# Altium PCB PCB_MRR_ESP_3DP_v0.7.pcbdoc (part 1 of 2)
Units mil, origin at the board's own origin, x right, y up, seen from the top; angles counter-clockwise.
Board outline 5220 x 5030 mil, 2 copper layers (Top Layer, Bottom Layer); 131 components, 154 nets, 480 pads, 88 vias.
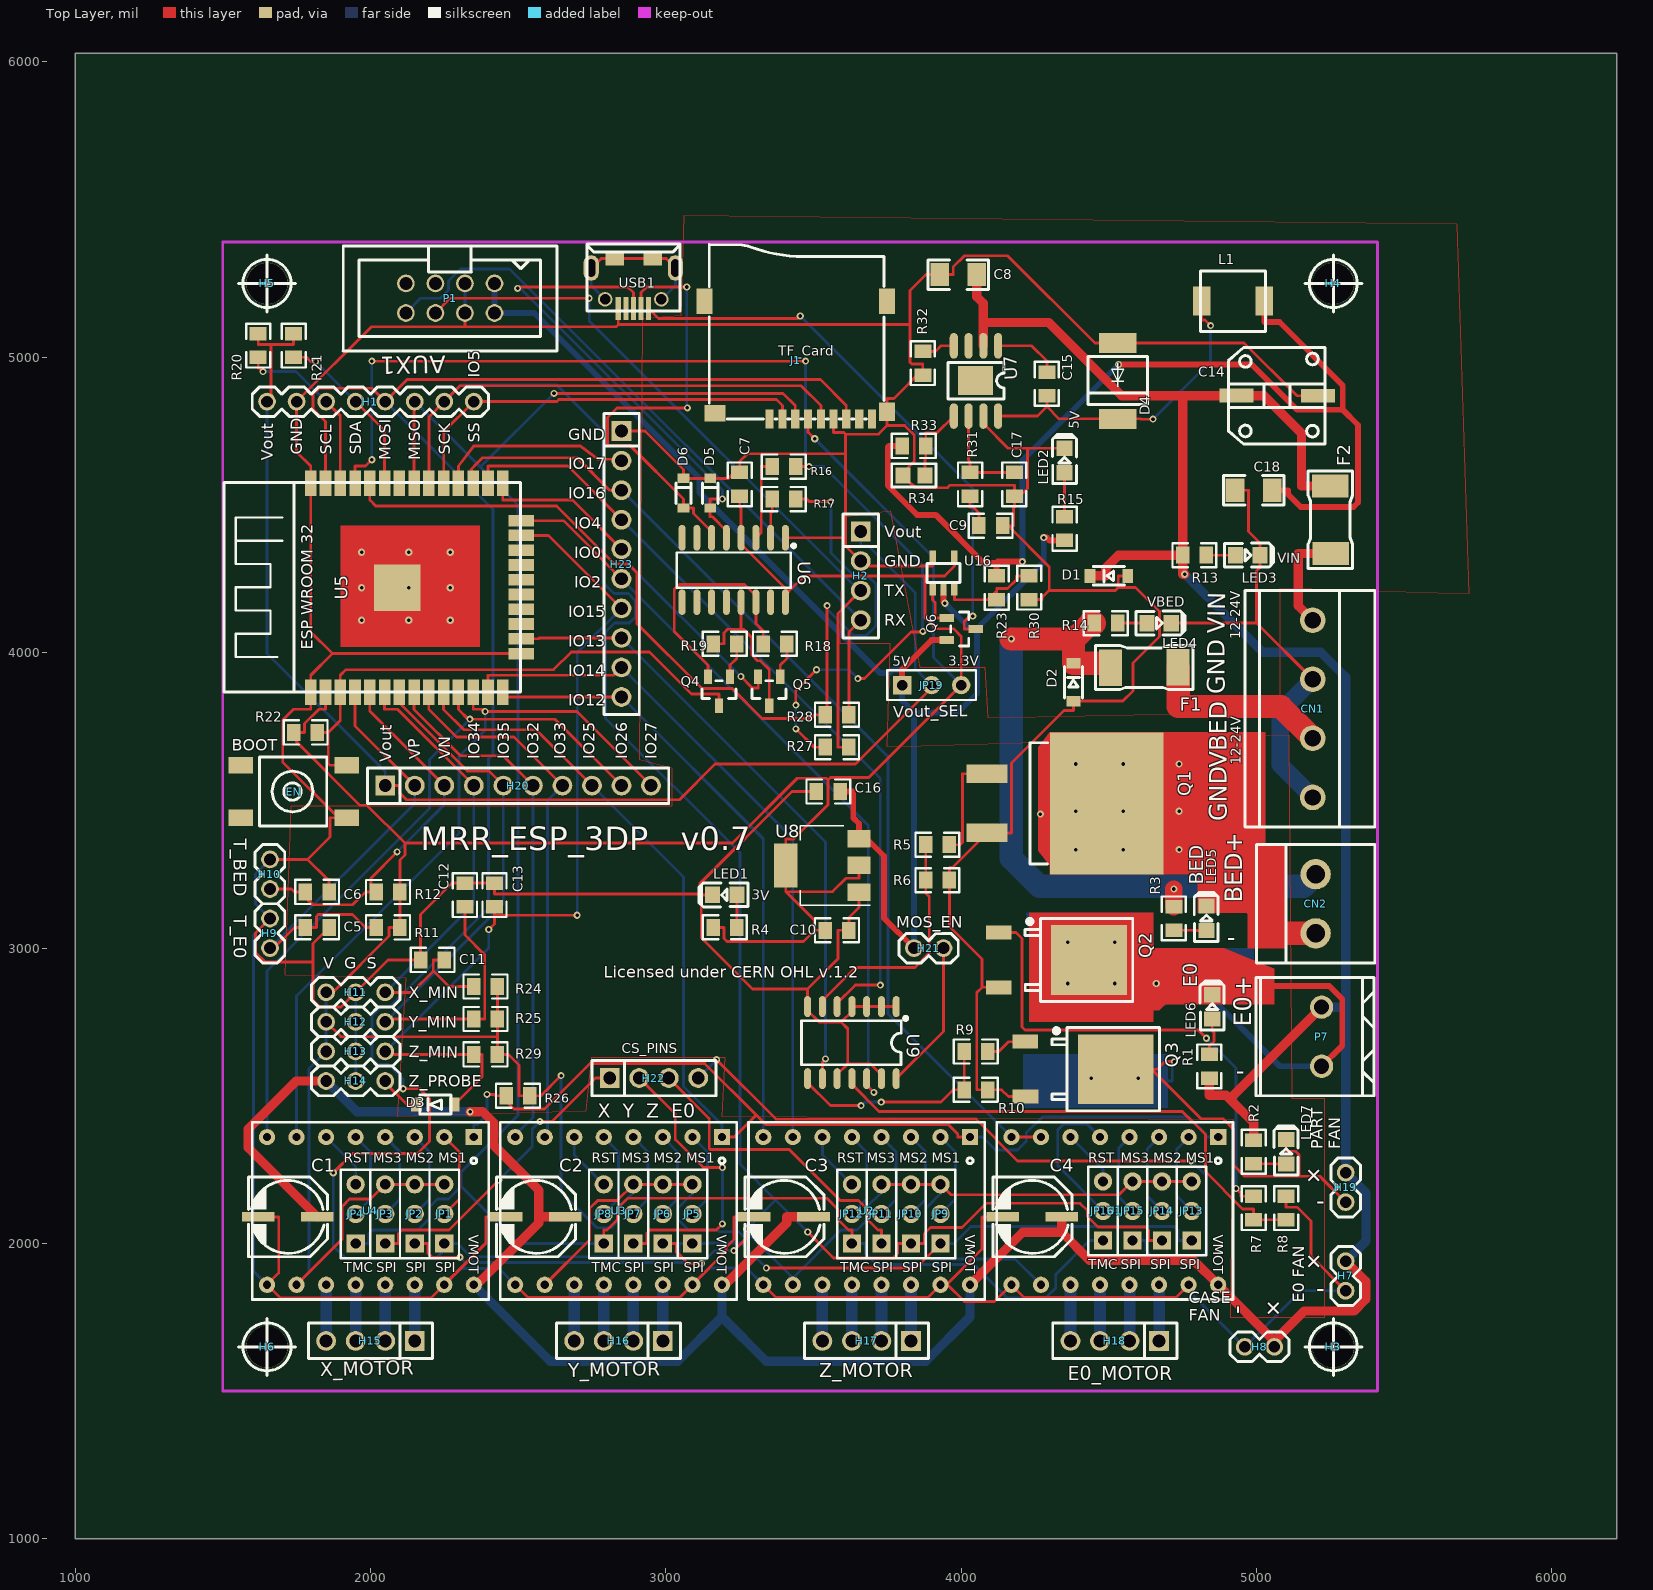
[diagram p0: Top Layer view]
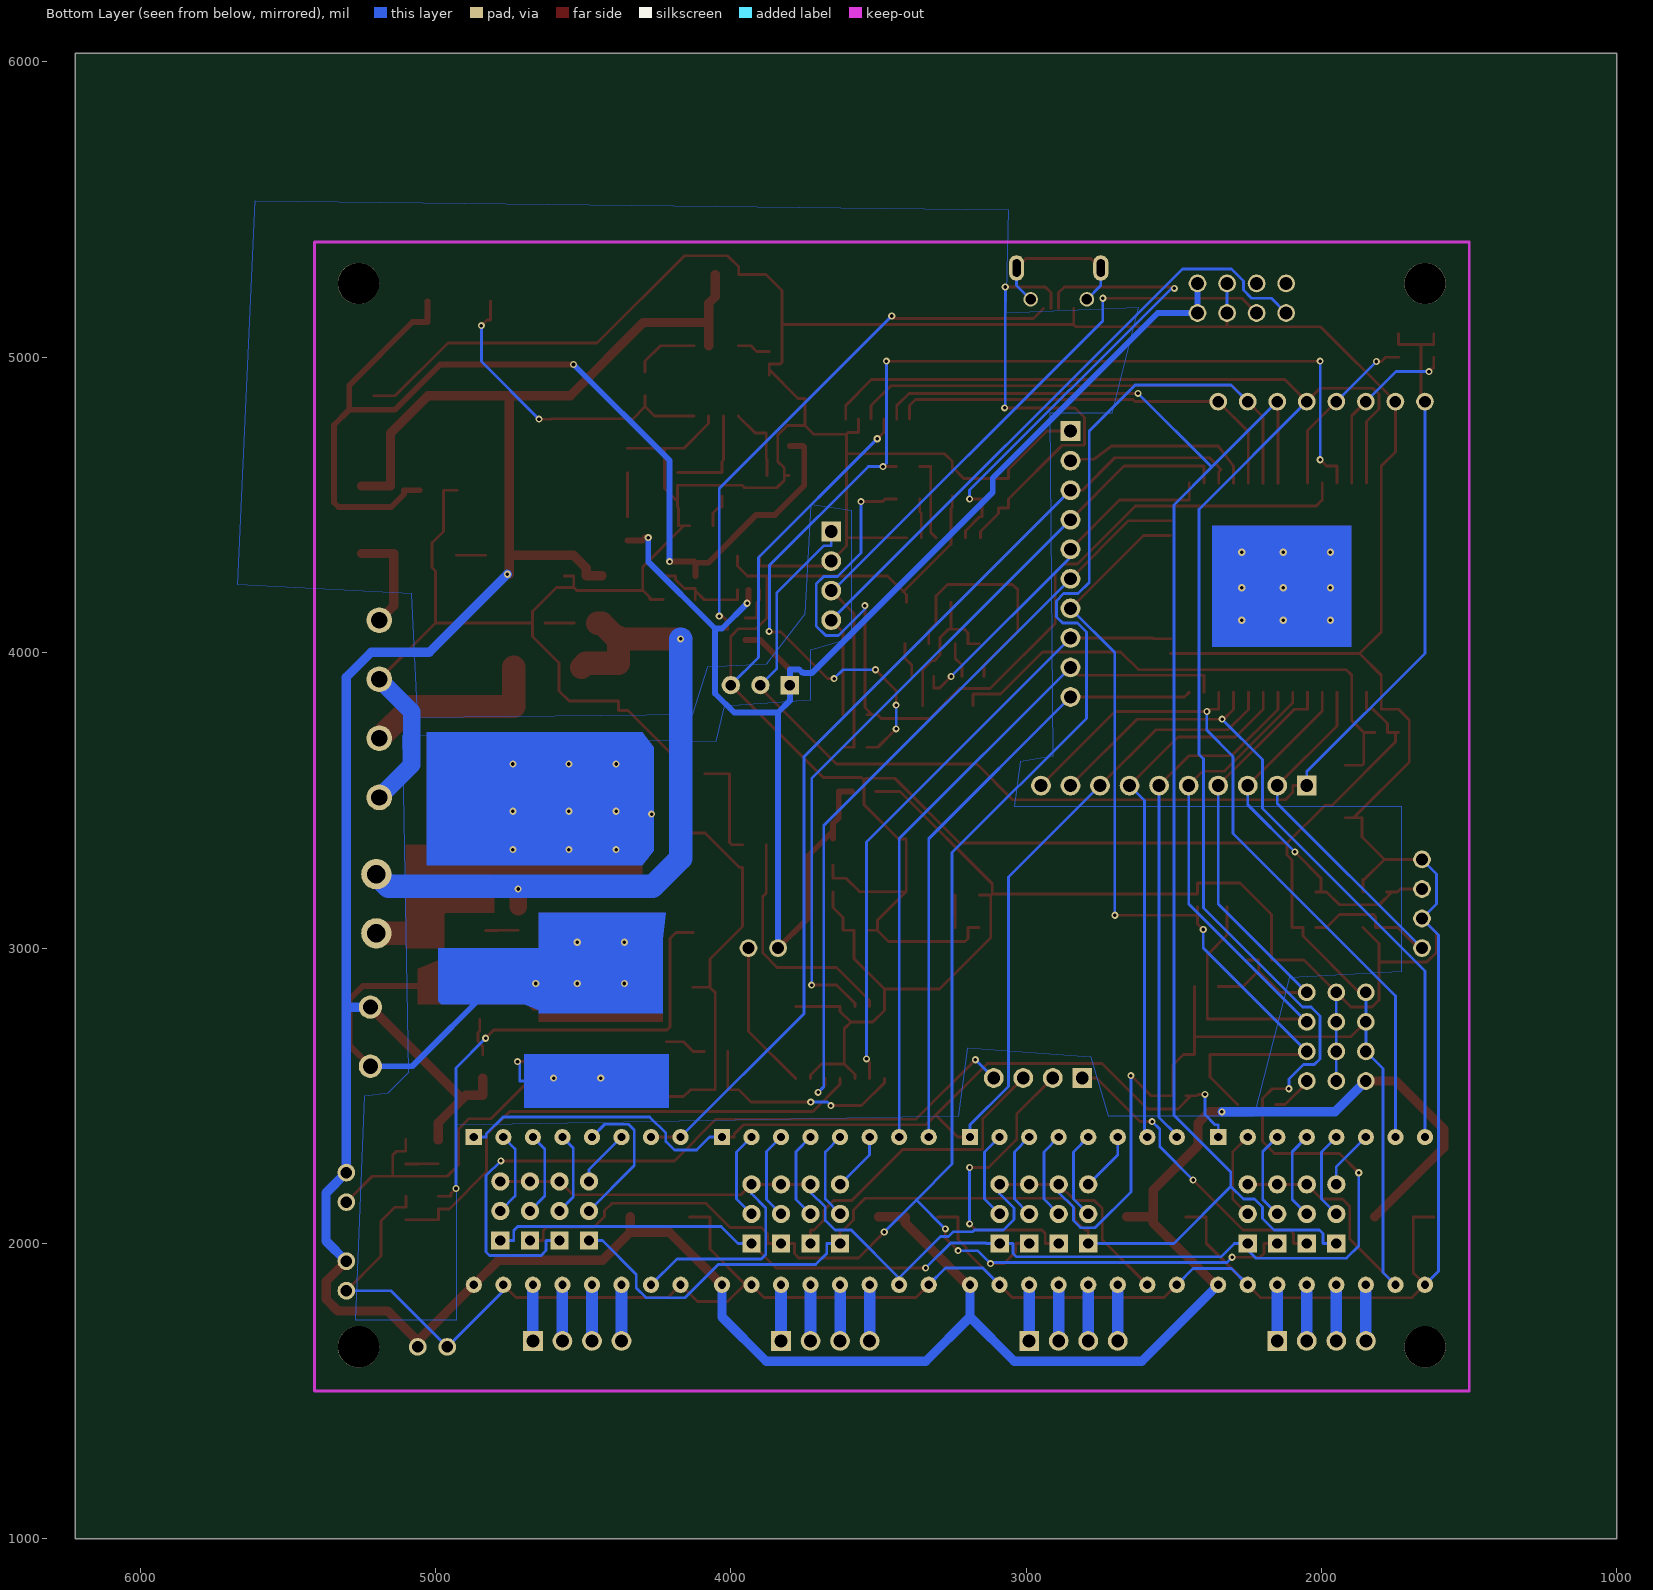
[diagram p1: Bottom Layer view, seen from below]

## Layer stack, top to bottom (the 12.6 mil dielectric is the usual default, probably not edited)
Top Layer: signal copper (thickness not stored)
Dielectric: dielectric 12.6, FR-4, Dk 4.8
Bottom Layer: signal copper (thickness not stored)

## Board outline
6220,1000 1000,1000 1000,6030 6220,6030

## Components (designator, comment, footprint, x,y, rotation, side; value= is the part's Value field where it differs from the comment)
C1 "100uF" CAP-D6.3XH7.7 1720,2090 r0 top
C2 "100uF" CAP-D6.3XH7.7 2560,2090 r0 top
C3 "100uF" CAP-D6.3XH7.7 3400,2090 r0 top
C4 "100uF" CAP-D6.3XH7.7 4240,2090 r0 top
C5 "10uF" 0805#1 1820,3070 r0 top
C6 "10uF" 0805#1 1820,3190 r0 top
C7 "1nF" 0805#1 3250,4570 r90 top
C8 "4.7uF" 1206 3990,5280 r180 top
C9 "820pF" 0805#1 4100,4430 r0 top
C10 "10uF" 0805#1 3580,3060 r0 top
C11 "100nF" 0805#1 2210,2960 r180 top
C12 "100nF" 0805#1 2320,3180 r90 top
C13 "100nF" 0805#1 2420,3180 r90 top
C14 "100uF" CAP-T-8*10 5070,4870 r0 top
C15 "100nF" 0805#1 4290,4910 r270 top
C16 "10uF" 0805#1 3550,3530 r180 top
C17 "56pF" 0805#1 4180,4570 r90 top
C18 "47uF" 1206 4990,4550 r0 top
CN1 "MKDS3/4-5.08" MKDS3/4-5.08 5190,3810 r90 top
CN2 "HEATBED" MKDS3/2-5.08 5200,3150 r0 top
D1 "1N4007" SOD-123F 4500,4260 r180 top
D2 "1N4007" SOD-123F 4380,3900 r90 top
D3 "1N4148W" SOD-123FL 2220,2470 r180 top
D4 "B540C-13-F" SMC(DO-214AB) 4530,4920 r270 top
D5 "PESD5V0S1BA" SOD-323 3150,4540 r90 top
D6 "PESD5V0S1BA" SOD-323 3060,4540 r90 top
EN "SWITCH,6*6*2.5,SMD" KEY-6.0*6.0 1740,3530 r0 top
F1 "0451020.MRL" SMF_045X 4620,3950 r180 top
F2 "0451003.MRL" SMF_045X 5250,4450 r90 top
H1 "I2C/SPI" 210S-1X8P 2000,4850 r0 top
H2 "Serial" DIP-1X4P-2.54MM-M 3660,4260 r270 top
H3 "HOLE" HOLE_3MM5 5260,1650 r0 top
H4 "HOLE" HOLE_3MM5 5260,5250 r0 top
H5 "HOLE" HOLE_3MM5 1650,5250 r0 top
H6 "HOLE" HOLE_3MM5 1650,1650 r0 top
H7 "FAN_HEATSINK" 210S-1X2P 5301.5,1889.9 r270 top
H8 "FAN_CASE" 210S-1X2P 5010,1650 r180 top
H9 "T_E0" 210S-1X2P 1660,3050 r90 top
H10 "T_BED" 210S-1X2P 1660,3250 r90 top
H11 "X_MIN" 210S-1X3P 1950,2850 r0 top
H12 "Y_MIN" 210S-1X3P 1950,2750 r0 top
H13 "Z_MIN" 210S-1X3P 1950,2650 r0 top
H14 "Z_PROBE" 210S-1X3P 1950,2550 r0 top
H15 "X_MOTOR" DIP-1X4P-2.54MM-M 2000,1670 r180 top
H16 "Y_MOTOR" DIP-1X4P-2.54MM-M 2840,1670 r180 top
H17 "Z_MOTOR" DIP-1X4P-2.54MM-M 3680,1670 r180 top
H18 "E0_MOTOR" DIP-1X4P-2.54MM-M 4520,1670 r180 top
H19 "FAN_E0" 210S-1X2P 5301.5,2189.9 r270 top
H20 "ESP_PINS1" DIP-1X10P-2.54MM-M 2500,3550 r0 top
H21 "MOSFET_ENABLE" 210S-1X2P 3890,3000 r0 top
H22 "CS_PINS" DIP-1X4P-2.54MM-M 2960,2560 r0 top
H23 "ESP_PINS2" DIP-1X10P-2.54MM-M 2850,4300 r270 top
J1 "Micro SD Card Holder" MICRO-SD9+4P-SMD-16.1X14.5X1.85MM 3440,4990 r90 top
JP1 "JP_X_MS1" HDR-3X1/2.54 2250,2100 r90 top
JP2 "JP_X_MS2" HDR-3X1/2.54 2150,2100 r90 top
JP3 "JP_X_MS3" HDR-3X1/2.54 2050,2100 r90 top
JP4 "JP_X_RST" HDR-3X1/2.54 1950,2100 r90 top
JP5 "JP_Y_MS1" HDR-3X1/2.54 3090,2100 r90 top
JP6 "JP_Y_MS2" HDR-3X1/2.54 2990,2100 r90 top
JP7 "JP_Y_MS3" HDR-3X1/2.54 2890,2100 r90 top
JP8 "JP_Y_RST" HDR-3X1/2.54 2790,2100 r90 top
JP9 "JP_Z_MS1" HDR-3X1/2.54 3930,2100 r90 top
JP10 "JP_Z_MS2" HDR-3X1/2.54 3830,2100 r90 top
JP11 "JP_Z_MS3" HDR-3X1/2.54 3730,2100 r90 top
JP12 "JP_Z_RST" HDR-3X1/2.54 3630,2100 r90 top
JP13 "JP_E0_MS1" HDR-3X1/2.54 4780,2110 r90 top
JP14 "JP_E0_MS2" HDR-3X1/2.54 4680,2110 r90 top
JP15 "JP_E0_MS3" HDR-3X1/2.54 4580,2110 r90 top
JP16 "JP_E0_RST" HDR-3X1/2.54 4480,2110 r90 top
JP19 "Vout_SEL" HDR-3X1/2.54 3900,3890 r0 top
L1 "4.7uH" 0530 4920,5190 r0 top
LED1 "LED_3V" LED-0805#1 3200,3180 r0 top
LED2 "LED_5V" LED-0805#1 4350,4650 r270 top
LED3 "LED_VIN" LED-0805#2 4970,4330 r180 top
LED4 "LED_VBED" LED-0805#2 4670,4100 r180 top
LED5 "BED" LED-0805#1 4830,3100 r270 top
LED6 "E0" LED-0805#1 4850,2800 r270 top
LED7 "FAN_E0" LED-0805#1 5100,2310 r270 top
P1 "AUX1" HDR-IDC-2.54-2X4P 2270,5200 r180 top
P7 "HOTEND_E0" WJ500V-5.08-2P 5220,2700 r90 top
Q1 "IRLS3034PBF" D2PAK 4290,3490 r270 top
Q2 "IRLR8743TRPBF" TO-252-2 4280,2960 r270 top
Q3 "IRLR8743TRPBF" TO-252-2 4370,2590 r270 top
Q4 "S9014" SOT-23(SOT-23-3) 3180,3870 r180 top
Q5 "S9014" SOT-23(SOT-23-3) 3350,3870 r180 top
Q6 "FDN340P" SOT-23(SOT-23-3) 4000,4080 r270 top
R1 "1.5KΩ(152)" 0805#1 4840,2600 r90 top
R2 "1.5KΩ(152)" 0805#1 4990,2310 r270 top
R3 "1.5KΩ(152)" 0805#1 4720,3100 r270 top
R4 "220Ω(221)" 0805#1 3200,3070 r0 top
R5 "10Ω(10R)" 0805#1 3920,3350 r0 top
R6 "100K" 0805#1 3920,3230 r0 top
R7 "10Ω(10R)" 0805#1 4990,2120 r90 top
R8 "100K" 0805#1 5100,2120 r90 top
R9 "10Ω(10R)" 0805#2 4050,2650 r0 top
R10 "100K" 0805#2 4050,2520 r0 top
R11 "4.7KΩ(472)" 0805#1 2060.01,3069.99 r0 top
R12 "4.7KΩ(472)" 0805#1 2060.01,3189.99 r0 top
R13 "2.2K" 0805#1 4790.01,4329.99 r0 top
R14 "2.2K" 0805#1 4490.01,4099.99 r0 top
R15 "330Ω(331)" 0805#1 4350,4420 r90 top
R16 "0Ω" 0805#1 3400,4630 r0 top
R17 "0Ω" 0805#1 3400,4520 r0 top
R18 "12KΩ(123)" 0805#1 3370,4030 r0 top
R19 "12KΩ(123)" 0805#1 3200,4030 r0 top
R20 "4.7KΩ(472)" 0805#1 1620,5040 r90 top
R21 "4.7KΩ(472)" 0805#1 1740,5040 r90 top
R22 "12KΩ(123)" 0805#1 1780,3730 r180 top
R23 "10KΩ" 0805#1 4120,4220 r90 top
R24 "10KΩ" 0805#1 2390,2870 r0 top
R25 "10KΩ" 0805#1 2390,2760 r0 top
R26 "10KΩ" 0805#1 2500,2500 r0 top
R27 "1KΩ" 0805#1 3580,3680 r0 top
R28 "1KΩ" 0805#1 3580,3790 r0 top
R29 "10KΩ" 0805#1 2390,2640 r0 top
R30 "47KΩ(473)" 0805#1 4230,4220 r270 top
R31 "23.7K" 0805#1 4030,4570 r90 top
R32 "73.2K" 0805#1 3870,4980 r270 top
R33 "60.4K" 0805#1 3840,4700 r0 top
R34 "11.5K" R0805 3840,4600 r180 top
U1 "POLULU_DRIVER" POLULU_DRIVER 4870,2360 r180 top
U2 "POLULU_DRIVER" POLULU_DRIVER 4030,2360 r180 top
U3 "POLULU_DRIVER" POLULU_DRIVER 3190,2360 r180 top
U4 "POLULU_DRIVER" POLULU_DRIVER 2350,2360 r180 top
U5 "ESP32-WROOM" ESP32_WROOM_FOOTPRINT 2090,4220 r90 top
U6 "CH340C" SOP-16_150MIL 3230,4280 r270 top
U7 "TPS54340DDAR" SOIC-8_150MIL-EP 4050,4920 r270 top
U8 "AMS1117-3.3" SOT-223 3530,3280 r180 top
U9 "74HCT125D,653" SOIC-14_150MIL 3630,2680 r270 top
U16 "MCP6001RT-I/OT" SOT-23-5 3940,4270 r0 top
USB1 "micro USBFemale" MICRO-USB-1 2890,5250 r90 top

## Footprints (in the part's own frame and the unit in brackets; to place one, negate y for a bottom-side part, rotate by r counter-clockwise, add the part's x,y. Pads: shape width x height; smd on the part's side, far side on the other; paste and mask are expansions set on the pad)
210S-1X2P [mil]
  round 60 hole 39.37: 1(-50,0) 2(50,0)
  silkscreen extent -100,-50 100,50
210S-1X3P [mil]
  round 60 hole 39.37: 1(-100,0) 2(0,0) 3(100,0)
  silkscreen extent -150,-50 150,50
210S-1X8P [mil]
  round 60 hole 39.37: 1(-350,0) 2(-250,0) 3(-150,0) 4(-50,0) 5(50,0) 6(150,0) 7(250,0) 8(350,0)
  silkscreen extent -400,-50 400,50
0530 [mm]
  rect 1.5x2.5 smd: 1(-2.7,0) 2(2.7,0)
  silkscreen extent -2.8,-2.6 2.8,2.6
0805#1 [mil]
  rect 45.67x57.87 smd: 1(-40,0) 2(40,0)
  silkscreen extent -75,-41 74,41
0805#2 [mil]
  rect 45.67x57.87 smd: 1(-40.05,0) 2(39.95,0)
  silkscreen extent -75,-41 74,41
1206 [mil]
  rect 63x78.74 smd: 1(-62.99,0) 2(62.99,0)
  silkscreen extent -103,-50 103,50
CAP-D6.3XH7.7 [mm]
  rect 2.8x0.8 smd: 1(2.54,0) 2(-2.54,0)
  silkscreen extent -3.37,-3.43 3.43,3.43
CAP-T-8*10 [mm]
  rect 2.9x1.2 smd: 1(-3.5,0.005) 2(3.5,-0.005)
  silkscreen extent -4.21,-4.16 4.1,4.15
D2PAK [mil]
  rect 63x137.8 smd: 1(-100,-202.5) 3(100,-202.5)
  rect 480.3x383.9 smd: 2(0.05,202.55)
  silkscreen extent -205,-57 205,2
DIP-1X4P-2.54MM-M [mm]
  rect 1.7x1.7 hole 1.1: 1(-3.81,0)
  round 1.7 hole 1.1: 2(-1.27,0) 3(1.27,0) 4(3.81,0)
  silkscreen extent -5.33,-1.52 5.33,1.52
DIP-1X10P-2.54MM-M [mm]
  rect 1.7x1.7 hole 1.1: 1(-11.43,0)
  round 1.7 hole 1.1: 2(-8.89,0) 3(-6.35,0) 4(-3.81,0) 5(-1.27,0) 6(1.27,0) 7(3.81,0) 8(6.35,0) 9(8.89,0) 10(11.43,0)
  silkscreen extent -12.95,-1.52 12.95,1.52
ESP32_WROOM_FOOTPRINT [mm]
  rect 2.2x1 smd: 1(-8.989,7.423) 2(-8.992,6.147) 3(-8.994,4.879) 4(-8.994,3.609) 5(-8.994,2.339) 6(-8.994,1.069) 7(-8.994,-0.201) 8(-8.997,-1.468) 9(-8.997,-2.738) 10(-8.997,-4.008) 11(-8.997,-5.278) 12(-8.994,-6.551) 13(-8.994,-7.821) 14(-8.994,-9.091) 25(8.992,-9.093) 26(8.992,-7.823) 27(8.992,-6.553) 28(8.989,-5.281) 29(8.989,-4.011) 30(8.989,-2.741) 31(8.989,-1.471) 32(8.992,-0.203) 33(8.992,1.067) 34(8.992,2.337) 35(8.992,3.607) 36(8.992,4.877) 37(8.994,6.144) 38(8.997,7.421)
  rect 1x2.2 smd: 15(-5.667,-10.693) 16(-4.397,-10.693) 17(-3.127,-10.693) 18(-1.859,-10.696) 19(-0.589,-10.696) 20(0.681,-10.696) 21(1.951,-10.696) 22(3.223,-10.693) 23(4.493,-10.693) 24(5.763,-10.693)
  rect 4x4 smd: 39(-0.001,-0.011)
  silkscreen extent -8.97,-10.63 9.03,14.87
HDR-3X1/2.54 [mil]
  rect 62x62 hole 35: 1(-100,0)
  round 62 hole 35: 2(0,0) 3(100,0)
  silkscreen extent -150,-50 150,50
HDR-IDC-2.54-2X4P [mil]
  round 60 hole 43.3: 1(-150,-50) 2(-150,50) 3(-50,-50) 4(-50,50) 5(50,-50) 6(50,50) 7(150,-50) 8(150,50)
  silkscreen extent -361,-177 362,178
HOLE_3MM5 [mil]
  round 140 hole 140: 1(0,0)
  silkscreen extent -96,-96 96,96
KEY-6.0*6.0 [mm]
  rect 2.1x1.4 smd: 1(4.55,-2.252) 2(-4.553,-2.252) 3(4.553,2.252) 4(-4.553,2.249)
  silkscreen extent -2.95,-2.95 2.85,2.95
LED-0805#1 [mil]
  rect 51.2x55.1 smd: 1(40.7,0.05) 2(-42,0.05)
  silkscreen extent -88,-41 78,40
LED-0805#2 [mil]
  rect 51.2x55.1 smd: 1(41.4,-0.05) 2(-41.3,-0.05)
  silkscreen extent -88,-41 78,40
MICRO-SD9+4P-SMD-16.1X14.5X1.85MM [mil]
  rect 63x27.6 smd: 1(-199,89) 2(-199,45) 3(-199,2) 4(-199,-41) 5(-199,-85) 6(-199,-128) 7(-199,-171) 8(-199,-215) 9(-199,-258)
  rect 63x55.1 smd: G1(-175,-309.05)
  rect 86.6x55.1 smd: G2(199,-309.05) G3(199,308.95)
  rect 55.1x70.9 smd: G4(-179.05,273.95)
  silkscreen extent -199,-298 392,293
MICRO-USB-1 [mm]
  round 1.25 hole 0.9: 0(-1.371,2.431) 0(-1.371,-2.41)
  oval 2.2x1.3 hole 0.7 slot 1.5 at 0 deg: 0(1.329,3.619) 0(1.329,-3.619)
  rect 1.2x1.6 smd: 0(2.14,-1.684) 0(2.156,1.595)
  rect 2x0.45 smd: 1(-2.156,-1.311) 2(-2.156,-0.66) 3(-2.156,-0.011) 4(-2.156,0.639) 5(-2.156,1.289)
  silkscreen extent -2.36,-4 3.4,4
MKDS3/2-5.08 [mm]
  round 2.6 hole 1.6: 1(0,-2.54) 2(0,2.54)
  silkscreen extent -5.08,-5.08 5.08,5.08
MKDS3/4-5.08 [mm]
  round 2.2 hole 1.4: 1(-7.62,0) 2(-2.54,0) 3(2.54,0) 4(7.62,0)
  silkscreen extent -10.16,-5.33 10.16,5.84
POLULU_DRIVER [mil]
  rect 55x55 hole 28: 1(0,0)
  round 55 hole 28: 2(100,0) 3(200,0) 4(300,0) 5(400,0) 6(500,0) 7(600,0) 8(700,0) 9(700,500) 10(600,500) 11(500,500) 12(400,500) 13(300,500) 14(200,500) 15(100,500) 16(0,500)
  silkscreen extent -50,-50 750,550
R0805 [mil]
  rect 51.2x55.1 smd: 1(-37.4,0) 2(37.4,0)
  silkscreen extent -75,-39 75,39
SMC(DO-214AB) [mil]
  rect 67.87x126 smd: 1(-128.4,0) 2(128.4,0)
  silkscreen extent -82,-100 81,100
SMF_045X [mil]
  rect 78.74x124.02 smd: 1(-114.35,-0.5) 2(114.35,0.5)
  silkscreen extent -165,-74 166,75
SOD-123F [mil]
  rect 35.8x48 smd: 1(-64,0) 2(64,0)
  silkscreen extent -53,-31 53,31
SOD-123FL [mil]
  rect 35.8x48 smd: 1(64,0) 2(-64,0)
  silkscreen extent -53,-32 53,32
SOD-323 [mm]
  rect 0.8x1 smd: 1(-1.269,0) 2(1.271,0)
  silkscreen extent -0.89,-0.66 0.89,0.66
SOIC-8_150MIL-EP [mm]
  oval 2.2x0.7 smd: 1(-3.023,1.905) 2(-3.023,0.635) 3(-3.023,-0.635) 4(-3.023,-1.905) 5(3.023,-1.905) 6(3.023,-0.635) 7(3.023,0.635) 8(3.023,1.905)
  rect 2.5x3 smd: 9(-0.025,-0.051)
  silkscreen extent -1.6,-2.41 1.55,2.41
SOIC-14_150MIL [mm]
  oval 1.8x0.6 smd: 1(-3.099,3.81) 2(-3.099,2.54) 3(-3.099,1.27) 4(-3.099,0) 5(-3.099,-1.27) 6(-3.099,-2.54) 7(-3.099,-3.81) 8(3.099,-3.81) 9(3.099,-2.54) 10(3.099,-1.27) 11(3.099,0) 12(3.099,1.27) 13(3.099,2.54) 14(3.099,3.81)
  silkscreen extent -2.23,-4.34 1.91,4.77
SOP-16_150MIL [mm]
  oval 2.2x0.6 smd: 1(-2.769,4.445) 2(-2.769,3.175) 3(-2.769,1.905) 4(-2.769,0.635) 5(-2.769,-0.635) 6(-2.769,-1.905) 7(-2.769,-3.175) 8(-2.769,-4.445) 9(2.769,-4.445) 10(2.769,-3.175) 11(2.769,-1.905) 12(2.769,-0.635) 13(2.769,0.635) 14(2.769,1.905) 15(2.769,3.175) 16(2.769,4.445)
  silkscreen extent -2.23,-4.9 1.52,5.3
SOT-23(SOT-23-3) [mm]
  rect 0.7x1.25 smd: 1(-0.95,-1.25) 2(0.95,-1.25) 3(0,1.25)
  silkscreen extent -1.46,-0.9 1.46,0.65
SOT-23-5 [mil]
  rect 21.7x39.37 smd: 1(-37,-57) 2(0,-57) 3(37,-57) 4(37,57) 5(-37,57)
  silkscreen extent -56,-32 56,32
SOT-223 [mm]
  rect 2x1.5 smd: 1(-3.15,2.3) 2(-3.15,0) 3(-3.15,-2.3)
  rect 2x3.8 smd: 4(3.15,0)
  silkscreen extent -4.1,-3.41 1.91,3.41
TO-252-2 [mm]
  rect 1.2x2.2 smd: 1(-2.362,-3.876) 3(2.362,-3.871)
  rect 6x6.5 smd: 4(0,3.877)
  silkscreen extent -3.57,-1.61 3.57,7.64
WJ500V-5.08-2P [mm]
  round 2 hole 1.3: 1(-2.54,0) 2(2.54,0)
  silkscreen extent -5.08,-4.52 5.08,5.64

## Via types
v1: diameter 24.02, hole 12.2, Top Layer to Bottom Layer, 71 vias
v2: diameter 24.4, hole 12, Top Layer to Bottom Layer, 17 vias

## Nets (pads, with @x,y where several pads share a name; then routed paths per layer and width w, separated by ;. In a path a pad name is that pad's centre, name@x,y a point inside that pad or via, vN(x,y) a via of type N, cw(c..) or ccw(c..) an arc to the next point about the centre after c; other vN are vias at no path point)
5V1: C18.2 L1.2 R23.2 R33.1 | length 3586.4
  Top Layer w19.68: R33.1@3800,4700 3755.5,4700 3751.4,4695.9 3751.4,4565.7 3850.7,4466.5 3913.5,4466.5 4075.5,4304.5 4120,4304.5 ; R23.2@4120,4259.99 4120,4304.5 ; v1(4207.1,4308.2) 4123.7,4308.2 4120,4304.5 ; v1(4532.4,4975.6) 4983.5,4975.6 5136.9,4822.1 5291.8,4822.1 ; L1.2@5026.3,5190 5026.3,5119.1 5077.5,5119.1 5291.8,4904.8 5291.8,4822.1 ; C18.2@5052.99,4550 5106.2,4550 5106.2,4536.7 5149.6,4493.2 5327.9,4493.2 5343.4,4508.7 5343.4,4770.5 5291.8,4822.1
  Bottom Layer w19.68: v1(4207.1,4308.2) 4207.1,4650.3 v1(4532.4,4975.6)
+3.3V: C7.1 C10.1 H11.1 H12.1 H13.1 J1.4 JP1.3 JP2.3 JP3.3 JP5.3 JP6.3 JP7.3 JP9.3 JP10.3 JP11.3 JP13.3 JP14.3 JP15.3 JP19.3 R4.1 R11.2 R12.2 R22.2 R24.2 R25.2 R26.2 R29.2 U1.10 U2.10 U3.10 U4.10 U5.2 U6.4 U6.16 U8.2 U8.4 U16.4 | length 14826.3
  Top Layer w9.45: R22.2@1740,3730 R22.2@1749.4,3730 ; U4.10@1750,1860 1904.7,2014.7 1904.7,2124.9 1929.8,2150 2000,2150 JP3.3@2050,2200 JP2.3@2150,2200 JP1.3@2250,2200 ; U5.2@1848,3866 1848,3808.4 1825.8,3808.4 1777.1,3759.7 1777.1,3730 R22.2@1749.4,3730 ; H12.1@1850,2750 1900,2700 2430,2700 ; H11.1@1850,2850 1872.5,2850 2062.9,3040.4 2062.9,3070 R11.2@2100,3070 R12.2@2100,3190 2100,3297.9 2116.7,3314.6 2116.7,3355.2 ; R24.2@2430,2870 R25.2@2430,2760 2430,2700 ; U3.10@2590,1860 2742.2,2012.1 2742.2,2117.9 2769.5,2145.3 2835.3,2145.3 JP7.3@2890,2200 JP6.3@2990,2200 JP5.3@3090,2200 ; v1(2645.4,2568.3) 2577.1,2500 R26.2@2540,2500 2502.9,2500 2502.9,2604.1 2467.1,2640 R29.2@2430,2640 2430,2700 ; R4.1@3159.99,3070.04 3197.1,3070 3197.1,3033 3207.5,3022.5 3465.5,3022.5 3502.9,3060 ; C7.1@3250,4530 3250,4511.5 3250,4492.9 3255,4487.9 U6.4@3255,4389 3255,4367.4 U6.16@3415.8,4206.6 ; U6.16@3405,4171 3405,4195.8 U6.16@3415.8,4206.6 ; J1.4@3481,4791 3481,4745.2 3483.1,4745.2 v1(3504.1,4724.3) ; C10.1@3540,3060 3502.9,3060 ; U8.2@3654,3280 3654,3236.2 3610.2,3236.2 3564.9,3190.9 3406,3190.9 ; JP11.3@3730,2200 JP10.3@3830,2200 JP9.3@3930,2200 3965.3,2164.7 4534.7,2164.7 JP15.3@4580,2210 JP14.3@4680,2210 JP13.3@4780,2210 ; U16.4@3977.1,4327 3977.1,4293 3944,4260 3877.9,4260 ; R22.2@1749.4,3730 1749.4,3698.5 1964.7,3483.2 1988.7,3483.2 2116.7,3355.2 ; 2116.7,3355.2 3225.4,3355.2 3444.8,3574.7 3543,3574.7 3548.8,3568.8 ; 3406,3190.9 U8.4@3406,3280 3406,3369.1 3432.8,3369.1 3548.8,3485.1 3548.8,3568.8 ; 3406,3190.9 3502.9,3094 3502.9,3060 ; U6.16@3415.8,4206.6 3469.2,4260 3877.9,4260 ; 3548.8,3568.8 3557.2,3577.2 3687.2,3577.2 JP19.3@4000,3890 4000,4055.3 3974.1,4081.2 3914.4,4081.2 3877.9,4117.6 3877.9,4260
  Bottom Layer w9.45: U4.10@1750,1860 1791.8,1901.8 1791.8,2591.8 H13.1@1850,2650 H12.1@1850,2750 H11.1@1850,2850 ; v1(2645.4,2568.3) 2645.4,2174.3 2766.3,2053.4 2815.7,2053.4 2840,2077.6 2840,2123.1 2890,2173.1 JP7.3@2890,2200 ; JP5.3@3090,2200 3090,2168.6 3041.7,2120.3 3041.7,2080.9 3077.3,2045.3 3175.4,2045.3 3180.8,2039.9 3246.1,2039.9 3262.9,2023.1 3289.8,2023.1 U2.10@3430,1882.9 ; U2.10@3430,1860 U2.10@3430,1882.9 ; v1(3504.1,4724.3) 3905.8,4322.6 3905.8,3984.2 JP19.3@4000,3890 ; JP11.3@3730,2200 3730,2173.1 3680,2123.1 3680,2077.6 3647.6,2045.3 3592.4,2045.3 U2.10@3430,1882.9 ; JP9.3@3930,2200 3930,2168.6 3881.7,2120.2 3881.7,1963.1 3897.1,1947.6 4182.4,1947.6 U1.10@4270,1860
+5V: C16.1 H21.1 JP19.1 P1.1 P1.2 Q6.2 R15.1 U8.3 U16.2 | length 5035.7
  Top Layer w19.68: C16.1@3590.01,3529.99 3634.5,3530 3634.5,3441.3 3654,3421.8 U8.3@3654,3396.2 ; U8.3@3654,3370.5 U8.3@3654,3396.2 ; JP19.1@3800,3890 3800,3942.7 3899.9,4042.6 3904.5,4042.6 Q6.2@3950.8,4042.6 ; H21.1@3840,3000 3738.8,3101.2 3738.8,3311.4 U8.3@3654,3396.2 ; U16.2@3940.1,4213 3940.1,4171.6 v1(3944.5,4167.2) ; v1(4279.3,4389.4) 4290,4389.4 4299.4,4380 R15.1@4350,4380
  Bottom Layer w19.68: P1.1@2420,5250 P1.2@2420,5150 2554.8,5150 3113.3,4591.5 3113.3,4543 3725.6,3930.7 3751.7,3930.7 3753.6,3932.6 3758.6,3932.6 3768.7,3942.7 3800,3942.7 JP19.1@3800,3890 3800,3837.3 3840,3797.3 ; H21.1@3840,3000 3840,3797.3 ; v1(3944.5,4167.2) 4030.1,4081.5 4053.4,4081.5 ; v1(4279.3,4389.4) 4279.3,4307.4 4053.4,4081.5 ; 3840,3797.3 3988.6,3797.3 4053.4,3862.1 4053.4,4081.5
COMP: C17.2 R31.2 U7.6 | length 343.1
  Top Layer w9.45: U7.6@4025,4801 4025,4652.1 4030,4647.1 R31.2@4030,4610 C17.2@4180,4610
D3_1: D3.1 H14.3 | length 142.8
  Top Layer w9.45: H14.3@2050,2550 2050,2543.8 2123.8,2470 D3.1@2156,2470
DTR: Q5.3 R19.1 U6.13 | length 536.8
  Top Layer w9.45: R19.1@3160,4030 3197.1,4030 3197.1,4067.1 3209.3,4079.3 3255,4079.3 ; U6.13@3255,4171 3255,4079.3 ; Q5.3@3350,3820.8 3350,3943.4 3321,3972.4 3311.3,3972.4 3291.5,3992.3 3291.5,4050.4 3262.6,4079.3 3255,4079.3
E0_CS: H22.4 JP15.1 | length 2458.6
  Top Layer w9.45: v1(3171.8,2621.8) 3372.9,2420.8 4049.8,2420.8 4191.1,2279.5 v1(4778.4,2279.5)
  Bottom Layer w9.45: H22.4@3110,2560 v1(3171.8,2621.8) ; JP15.1@4580,2010 4625.3,2010 4625.3,1976.1 4641.7,1959.7 4816.9,1959.7 4828.3,1971 4828.3,2229.6 v1(4778.4,2279.5)
E0_DIR_PIN: H23.2 U5.28 | length 660.6
  Top Layer w9.45: U5.28@2297.9,4573.9 2297.9,4631.5 2350,4700 2710,4700 2770.5,4655 2845,4655 H23.2@2850,4650
E0_MS1: JP13.2 U1.2 | length 287.3
  Bottom Layer w9.45: U1.2@4770,2360 4730,2320 4730,2160 JP13.2@4780,2110
E0_MS2: JP14.2 U1.3 | length 287.3
  Bottom Layer w9.45: U1.3@4670,2360 4630,2320 4630,2160 JP14.2@4680,2110
E0_MS3: JP15.2 U1.4 | length 284.6
  Bottom Layer w9.45: U1.4@4570,2360 4533.2,2323.2 4533.2,2156.8 JP15.2@4580,2110
E0_RST: JP16.2 U1.5 | length 506.9
  Bottom Layer w9.45: U1.5@4470,2360 4426.6,2403.4 4345.9,2403.4 4326.7,2384.2 4326.7,2263.3 JP16.2@4480,2110
E0_SLP: JP16.3 U1.6 | length 195.6
  Bottom Layer w9.45: U1.6@4370,2360 4480,2250 JP16.3@4480,2210
E0_STEP_PIN: H23.3 U1.7 U1.8 U5.27 | length 3458.2
  Top Layer w9.45: U5.27@2348,4574 2348,4612 2340,4620 2360,4640 2380,4660 2700,4660 2810,4550 H23.3@2850,4550 ; U1.8@4170,2360 U1.7@4270,2360
  Bottom Layer w9.45: H23.3@2850,4550 3752.5,3647.5 3752.5,2777.5 U1.8@4170,2360
EN: EN.3 Q4.3 R22.1 U5.3 | length 1830
  Top Layer w9.45: R22.1@1820,3730 1838.5,3730 1857.1,3730 ; EN.3@1919.3,3618.6 1863.6,3618.6 1857.1,3625.2 1857.1,3730 ; Q4.3@3180,3820.8 3180,3859.7 3087.4,3859.7 2944.8,4002.3 2680.1,4002.3 2620.4,3942.5 1916.9,3942.5 1897.9,3923.5 U5.3@1897.9,3865.9 1897.9,3837.1 1897.9,3808.3 1897.9,3770.8 1857.1,3730
EN_2: EN.2
EN_4: EN.4
F1_1: CN1.2 F1.1 | length 633.1
  Top Layer w78.74: F1.1@4734.35,3950.5 4734.4,3817.6 5082.4,3817.6 CN1.2@5190,3710
F2_1: CN1.4 F2.1 | length 355.1
  Top Layer w31.5: CN1.4@5190,4110 5141.2,4158.8 5141.2,4335.6 F2.1@5250.5,4335.65
FAN_E0_PIN: H23.8 U5.16 U9.9 | length 2122.8
  Top Layer w9.45: U5.16@2511,4046.9 2568.6,4046.9 2571.7,4050 H23.8@2850,4050 ; U9.9@3530,2558 3530,2614.1 v1(3540.7,2624.8)
  Bottom Layer w9.45: H23.8@2850,4050 3540.7,3359.3 v1(3540.7,2624.8)
FB: R33.2 R34.1 U7.5 | length 263.2
  Top Layer w9.45: R34.1@3877.4,4600 3877.4,4654.2 3880,4656.8 R33.2@3880,4700 3880,4743.2 3917.2,4743.2 U7.5@3975,4801
GND: C1.2 C2.2 C3.2 C4.2 C5.2 C6.2 C7.2 C8.2 C9.2 C10.2 C11.2 C12.2 C13.2 C14.2 C16.2 C17.1 C18.1 CN1.1 CN1.3 D1.1 D2.1 D4.1 D5.2 D6.2 EN.1 H1.2 H2.2 H7.2 H8.2 H9.2 H10.2 H11.2 H12.2 H13.2 H14.2 H23.1 J1.6 J1.G1 LED1.2 LED2.2 LED3.2 LED4.2 P1.3 P1.4 Q1.3 Q2.3 Q3.3 R6.2 R8.2 R10.2 R30.2 R32.2 R34.2 U1.9 U1.15 U2.9 U2.15 U3.9 U3.15 U4.9 U4.15 U5.1 U5.15 U5.38 U6.1 U7.7 U8.1 U9.1 U9.2 U9.3 U9.4 U9.7 U9.10 U9.13 U16.5 USB1.5 | length 28009.5
  Top Layer w9.45: C1.2@1620,2090 1689.4,2090 1689.4,1899.4 U4.9@1650,1860 1693.5,1816.5 2206.5,1816.5 U4.15@2250,1860 2390.6,2000.6 2390.6,2090 C2.2@2460,2090 ; H9.2@1660,3100 1611.2,3051.2 1611.2,2985.1 1644,2952.4 1805.7,2952.4 ; H10.2@1660,3300 1787.1,3300 ; C5.2@1860,3070 1805.7,3015.7 1805.7,2952.4 ; C6.2@1860,3190 1860,3233.2 1853.9,3233.2 1787.1,3300 ; EN.1@1919.2,3441.3 EN.1@1891.4,3441.3 ; P1.4@2320,5150 2320,5103.2 ; U3.9@2490,1860 2532.9,1817.1 3047.1,1817.1 U3.15@3090,1860 3204.2,1974.2 3204.2,1986.5 3230.6,2012.9 3230.6,2090 C3.2@3300,2090 ; U5.15@2511,3996.9 1871,3996.9 ; USB1.5@2839.3,5165.1 2839.3,5111.4 ; H23.1@2850,4750 2930.1,4750 3060,4620.1 3060,4612 3060,4605 D6.2@3060,4590.05 D5.2@3150,4590.05 3211.5,4590 C7.2@3250,4628.5 ; LED1.2@3158,3180.05 3120.3,3180 ; C7.2@3250,4610 C7.2@3250,4628.5 ; U2.9@3330,1860 3372.9,1817.1 3887.1,1817.1 U2.15@3930,1860 3950,1860 U2.15@3951.8,1861.8 ; U6.1@3405,4389 3608.3,4389 ; C16.2@3510.01,3529.99 3427.1,3530 3114.9,3217.8 3114.9,3182.9 ; J1.6@3568,4791 3568,4745.2 3602.8,4745.2 3608.3,4739.8 ; U9.10@3580,2558 3580,2571.9 3615.8,2607.7 ; U8.1@3654,3189.45 3654,3137.2 3620,3103.2 C10.2@3620,3060 3582.9,3060 3582.9,2963.9 3480,2861 ; U9.13@3730,2558 3730,2570.4 3692.7,2607.7 3615.8,2607.7 ; U9.1@3780,2802 U9.2@3730,2802 U9.3@3680,2802 U9.4@3630,2802 3630,2785.7 3593.6,2749.3 ; R34.2@3802.6,4600 R34.2@3818.8,4600 ; R32.2@3870,4940 R32.2@3870,4958.5 ; U16.5@3903.1,4327 3903.1,4293 3677,4293 H2.2@3660,4310 3608.3,4361.7 3608.3,4389 ; U7.7@4075,4801 4075,4775.5 4158.5,4692 4224.2,4692 ; Q2.3@4127.6,2867 4070,2867 ; C4.2@4140,2090 4070.6,2090 4070.6,1980.7 U2.15@3951.8,1861.8 ; C9.2@4140,4430 C9.2@4158.6,4430 ; Q3.3@4217.6,2497 4160,2497 4137,2520 R10.2@4089.95,2520 4052.8,2520 4052.8,2849.8 4070,2867 ; R30.2@4230.01,4180 4273.2,4180 4273.2,4186.2 4297.8,4210.8 ; LED2.2@4350.1,4692 4224.2,4692 ; D1.1@4564,4260 4531.8,4260 4531.8,4221 ; U1.15@4770,1860 4727.6,1817.5 4212.5,1817.5 U1.9@4170,1860 4113,1803 4010.6,1803 U2.15@3951.8,1861.8 ; C18.1@4927.01,4550 4972.8,4550 4972.8,4410.4 5011.3,4371.9 LED3.2@5011.3,4330.05 5011.3,4288.2 5000,4276.9 5000,4100 ; R8.2@5100,2159.9 5100,2122.8 5137.1,2122.8 5184.3,2075.7 5184.3,1957.1 H7.2@5301.5,1839.9 ; CN1.3@5190,3910 5000,4100 ; C14.2@5207.8,4869.8 5136.4,4869.8 4957.8,5048.4 D4.1@4530,5048.4 4452.7,5048.4 4157.3,5343.8 4010.9,5343.8 3972.8,5305.7 3972.8,5280 C8.2@3927.01,5280 3881.3,5280 3826.8,5225.5 3826.8,5111.4 ; 1787.1,3300 1863.5,3376.5 1863.5,3441.3 EN.1@1891.4,3441.3 ; 1805.7,2952.4 1805.7,2823.6 1829.3,2800 1900,2800 H11.2@1950,2850 2060,2960 C11.2@2170,2960 2170,3113.2 2276.8,3220 C12.2@2320,3220 C13.2@2420,3220 2420,3182.9 3114.9,3182.9 ; 1871,3996.9 1797.8,3923.7 U5.1@1797.75,3866.1 1797.8,3808.5 1740.2,3808.5 1702.9,3771.3 1702.9,3629.8 EN.1@1891.4,3441.3 ; 1871,3996.9 1797.9,4070 1797.9,4574.2 1797.9,4631.8 1750,4679.6 H1.2@1750,4850 2003.2,5103.2 2320,5103.2 ; 2320,5103.2 2831,5103.2 2839.3,5111.4 ; 2839.3,5111.4 3826.8,5111.4 ; 3114.9,3182.9 3117.8,3180 3120.3,3180 ; 3120.3,3180 3120.3,3034.7 3294,2861 3480,2861 ; C7.2@3250,4628.5 3250,4647.1 3276.4,4673.5 3608.3,4673.5 ; 3480,2861 U9.7@3480,2802 3480,2788.7 3519.5,2749.3 3593.6,2749.3 ; 3593.6,2749.3 3615.8,2727 3615.8,2607.7 ; 3608.3,4389 3608.3,4673.5 ; 3608.3,4673.5 3608.3,4739.8 ; 3608.3,4739.8 3719.9,4739.8 3749.1,4769 ; 3749.1,4769 3808.6,4769 3841.2,4736.4 3841.2,4647.7 3818.8,4625.3 R34.2@3818.8,4600 ; 3749.1,4769 3749.1,4815 3749.1,4860.8 3772.2,4860.8 R32.2@3870,4958.5 ; R34.2@3818.8,4600 3818.8,4583.8 3844.4,4558.2 3953.3,4558.2 3962.2,4567.1 4180,4567.1 C17.1@4180,4530 4180,4520.7 C17.1@4180,4511.4 ; 3826.8,5111.4 3826.8,4983.2 3832.9,4977.1 3870,4977.1 R32.2@3870,4958.5 ; 4070,2867 4070,2962.8 3960,3072.9 R6.2@3960,3230 3960,3251.5 3960,3273.2 3970.7,3273.2 Q1.3@4087.5,3390 4170.7,3390 4170.7,3626.7 4347.8,3803.8 4380,3803.8 D2.1@4380,3836 4547.1,3836 4581.3,3870.2 4581.3,3965.1 4671.4,4055.3 4671.4,4100 ; C9.2@4158.6,4430 4297.8,4290.8 4297.8,4210.8 ; C9.2@4158.6,4430 4177.1,4430 4177.1,4490 4180,4492.9 C17.1@4180,4511.4 ; C17.1@4180,4511.4 4224.2,4555.6 4224.2,4692 ; 4297.8,4210.8 4521.6,4210.8 4531.8,4221 ; 4531.8,4221 4590.3,4221 4671.4,4139.9 4671.4,4100 ; 4671.4,4100 LED4.2@4711.3,4100.05 5000,4100
  Bottom Layer w9.45: U4.9@1650,1860 1604.3,1905.7 1604.3,3044.3 H9.2@1660,3100 1611.2,3148.8 1611.2,3251.2 H10.2@1660,3300 ; H14.2@1950,2550 H13.2@1950,2650 H12.2@1950,2750 H11.2@1950,2850 ; U4.15@2250,1860 2305.3,1915.3 2434.7,1915.3 U3.9@2490,1860 ; P1.4@2320,5150 P1.3@2320,5250 ; U3.15@3090,1860 3147.1,1917.1 3272.9,1917.1 U2.9@3330,1860 ; U1.15@4770,1860 4770,1840 H8.2@4960,1650 5149.9,1839.9 H7.2@5301.5,1839.9
  Bottom Layer w59.05: CN1.1@5190,3510 5080,3620 5080,3800 CN1.3@5190,3910
H21_2: H21.2 U9.14 | length 508.3
  Top Layer w9.45: U9.14@3780,2558 3940,2718 H21.2@3940,3000
HEATER_BED_PIN: H23.4 U5.26 U9.5 | length 2705.9
  Top Layer w9.45: U5.26@2398,4574 2398,4631.6 2668.4,4631.6 H23.4@2850,4450 ; U9.5@3580,2802 3580,2813 3641.6,2874.6 v1(3726.2,2874.6)
  Bottom Layer w9.45: H23.4@2850,4450 3726.2,3573.8 v1(3726.2,2874.6)
HEATER_E0_PIN: H23.6 U5.24 U9.12 | length 2569.6
  Top Layer w9.45: U5.24@2511,4446.9 2653.1,4446.9 H23.6@2850,4250 ; U9.12@3680,2558 3680,2535.9 v1(3704.4,2511.5)
  Bottom Layer w9.45: H23.6@2850,4250 3685.4,3414.6 3685.4,2530.5 v1(3704.4,2511.5)
IO0: H23.5 Q5.2 U5.25 | length 1240.4
  Top Layer w9.45: U5.25@2448,4574 2448,4516.4 2683.6,4516.4 H23.5@2850,4350 ; v1(3253.9,3919.2) 3292.7,3880.3 3312.6,3880.3 Q5.2@3312.6,3919.2
  Bottom Layer w9.45: H23.5@2850,4350 2850,4323 v1(3253.9,3919.2)
J1_1: J1.1
J1_8: J1.8
J1_9: J1.9
J1_G2: J1.G2
J1_G3: J1.G3
J1_G4: J1.G4
LED1_1: LED1.1 R4.2 | length 110.3
  Top Layer w9.45: R4.2@3239.99,3070.04 3240,3113.3 3240.7,3114 LED1.1@3240.7,3180.05
LED2_1: LED2.1 R15.2 | length 149.4
  Top Layer w9.45: R15.2@4350,4460 4350,4569.4 4350.1,4569.4 LED2.1@4350.1,4609.3
LED3_1: LED3.1 R13.2 | length 98.6
  Top Layer w9.45: R13.2@4830,4330 4888.7,4330 LED3.1@4928.6,4330.05
LED4_1: LED4.1 R14.2 | length 98.6
  Top Layer w9.45: R14.2@4530,4100 4588.7,4100 LED4.1@4628.6,4100.05
LED5_1: LED5.1 R3.2 | length 110.4
  Top Layer w9.45: R3.2@4720,3060 4787.5,3060 4788.2,3059.3 LED5.1@4830.1,3059.3
LED5_2: CN2.1 LED5.2 Q1.2 | length 1585.5
  Top Layer w9.45: v1(4268,3453.2) 4286.3,3471.6 4286.3,3489.9 4492.6,3489.9 4698.8,3489.9 4698.8,3437.2 4712,3424 4906.5,3229.5 4906.5,3176.7 ; LED5.2@4830.1,3142 4871.9,3142 4906.5,3176.7 ; 4961.7,3176.7 4906.5,3176.7
  Top Layer w78.74: 4961.7,3176.7 5088.3,3050 CN2.1@5200,3050
  Bottom Layer w9.45: v1(4268,3453.2) 4318.1,3503.3 4540,3503.3
  other v1: 4388,3333.2 4548,3333.2 4738,3333.2 4388,3463.2 4548,3463.2 4738,3463.2 4388,3623.2 4548,3623.2 4738,3623.2
LED6_1: LED6.1 R1.2 | length 128.6
  Top Layer w9.45: R1.2@4840,2640 4840,2667.5 4856.3,2683.8 4856.3,2713.2 4850.1,2719.4 LED6.1@4850.1,2759.3
LED7_1: LED7.1 R2.2 | length 110.3
  Top Layer w9.45: R2.2@4990.1,2270 5057.5,2270 5058.2,2269.3 LED7.1@5100.1,2269.3
LED7_2: H19.2 LED7.2 Q3.4 | length 1614.6
  Top Layer w9.45: Q3.4@4522.7,2590 Q3.4@4643.5,2590 ; v1(4722.2,2615.5) 4690.3,2615.5 4664.9,2590 Q3.4@4643.5,2590 ; LED7.2@5100.1,2352 5100.1,2312.1 5132.3,2312.1 5144.2,2300.2 5144.2,2227.7 ; H19.2@5301.5,2139.9 5213.7,2227.7 5144.2,2227.7 ; Q3.4@4643.5,2590 4811.1,2422.4 4885.8,2422.4 4921.7,2386.5 4921.7,2265.9 4959.9,2227.7 5144.2,2227.7
  Bottom Layer w9.45: 4455,2550 4714.3,2550 4714.3,2607.5 v1(4722.2,2615.5)
  other v2: 4440,2560 4600,2560
MISO: H1.6 J1.3 JP4.1 JP8.1 JP12.1 JP16.1 U5.31 | length 7548.5
  Top Layer w9.45: U5.31@2147.9,4573.9 2147.9,4847.9 H1.6@2150,4850 ; v1(2621.5,4877.6) 3397.2,4877.6 3438,4836.8 J1.3@3438,4791 ; JP8.1@2790,2000 2790,2045.3 2801.3,2045.3 2835.3,2079.2 2835.3,2116.8 2871.8,2153.3 3544.8,2153.3 3584.7,2113.4 3584.7,2079.2 3618.7,2045.3 3630,2045.3 JP12.1@3630,2000
  Bottom Layer w9.45: JP4.1@1950,2000 1995.3,2000 1995.3,2033.9 2006.6,2045.3 2161.1,2045.3 2200,2084.2 2200,2123.1 2226.9,2150 2264.5,2150 2307.3,2192.8 ; H1.6@2150,4850 2372,4628 ; v1(2621.5,4877.6) 2372,4628 ; JP8.1@2790,2000 2500.1,2000 2307.3,2192.8 ; JP12.1@3630,2000 3675.3,2000 3675.3,1966.1 3712.7,1928.6 4042.3,1928.6 4154.4,1816.5 4287.2,1816.5 4320,1849.4 4320,1895.3 4434.7,2010 JP16.1@4480,2010 ; 2307.3,2192.8 2307.3,2241.4 2500,2434.1 2500,4500 2372,4628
